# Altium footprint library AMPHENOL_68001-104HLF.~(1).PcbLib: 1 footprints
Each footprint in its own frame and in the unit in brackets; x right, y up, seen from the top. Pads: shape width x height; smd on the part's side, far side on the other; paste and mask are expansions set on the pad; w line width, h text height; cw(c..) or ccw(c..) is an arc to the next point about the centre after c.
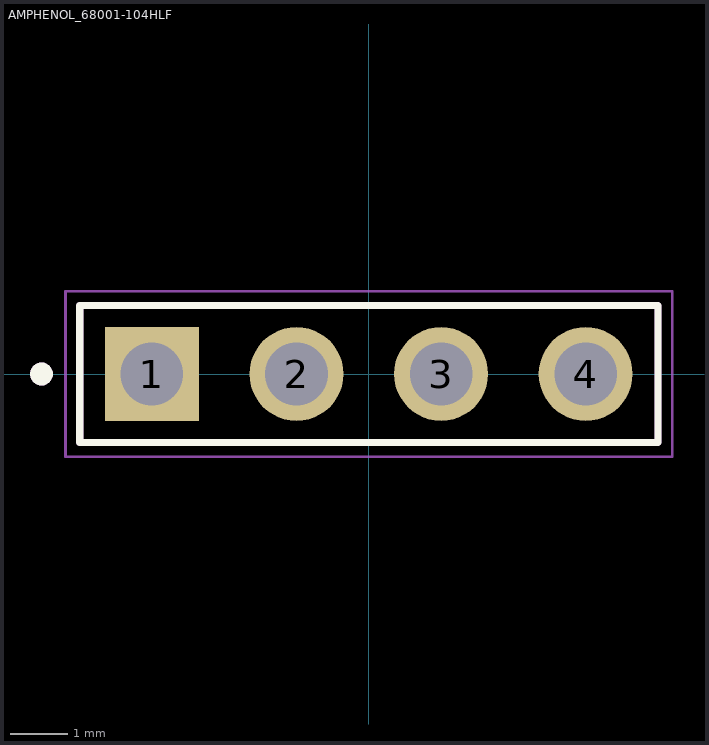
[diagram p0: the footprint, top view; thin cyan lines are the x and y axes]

## AMPHENOL_68001-104HLF [mm]
height 8.89
pads (4):
  rect 1.65x1.65 / inner round 1.65 / far side rect 1.65x1.65 hole 1.1: 1(-3.81,0)
  round 1.65 hole 1.1: 2(-1.27,0) 3(1.27,0) 4(3.81,0)
Top Overlay:
  circle w0.2: c-5.75,0 r0.1
  lines w0.127: -5.08,-1.205 -5.08,1.205 5.08,1.205 5.08,-1.205 -5.08,-1.205
Mechanical 13:
  circle w0.2: c-5.75,0 r0.1
  lines w0.127: -5.08,-1.205 -5.08,1.205 5.08,1.205 5.08,-1.205 -5.08,-1.205
Mechanical 15:
  lines w0.05: -5.33,-1.455 -5.33,1.455 5.33,1.455 5.33,-1.455 -5.33,-1.455
3D body "step_temp.STEP": height 8.38, standoff -3.05, extent -5.08,-1.205 5.08,1.205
